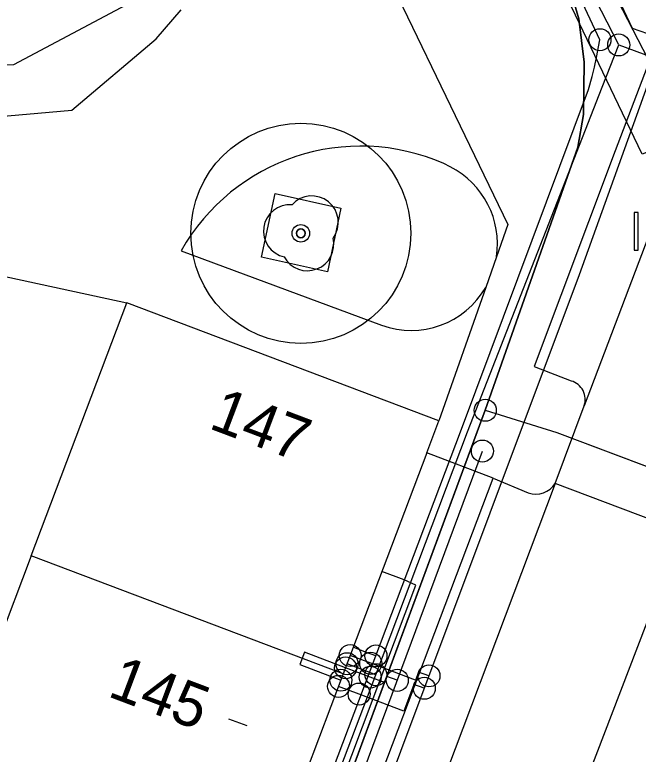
# Model space of a CAD drawing. Extents: x 192672 to 192910, y 446344 to 446512.
# Drawn here: x 192758.05 to 192772.22, y 446479 to 446495.79 of the extents above; entities that cross this region are included whole.
import ezdxf

# ---------------------------------------------------------------- set-up
doc = ezdxf.new("R2010")
doc.units = 0
for name, color, linetype in [('( Toegevoegd 29-11-2021 14_41_42) wegdeel vlak', 7, 'Continuous'), ('B-GV-GR-BOOM-S', 7, 'Continuous'), ('B-OI-KL-()_FIREHYDRANT_WATER-S', 7, 'Continuous'), ('B-OI-KL-()_MANTELBUIS_WATER-G', 7, 'Continuous'), ('B-OI-KL-()_PUNTVANLEVERING_WATER-S', 7, 'Continuous'), ('B-OI-KL-BUISLEIDING_OLIEGASCHEMICALIEN_GASLAGEDRUK-G', 7, 'Continuous'), ('B-OI-KL-DATA-G', 7, 'Continuous'), ('B-OI-KL-DATA_DUCT-G', 7, 'Continuous'), ('B-OI-KL-DATA_GTWP-S', 7, 'Continuous'), ('B-OI-KL-DATA_HULPSTUK-S', 7, 'Continuous'), ('B-OI-KL-DATA_KABELBED-G', 7, 'Continuous'), ('B-OI-KL-DATA_MANTELBUIS-G', 7, 'Continuous'), ('B-OI-KL-DATA_MOF-S', 7, 'Continuous'), ('B-OI-KL-ET_LS-G', 7, 'Continuous'), ('B-OI-KL-ET_LS_DELIVERYPOINT-S', 7, 'Continuous'), ('B-OI-KL-ET_LS_MOF-S', 7, 'Continuous'), ('B-OI-KL-GAS_LD_AFTAKZADEL-S', 7, 'Continuous'), ('B-OI-KL-GAS_LD_DELIVERYPOINT-S', 7, 'Continuous'), ('B-OI-KL-GAS_LD_OVERGANGSSTUK-S', 7, 'Continuous'), ('B-OI-KL-WATER-G', 7, 'Continuous'), ('B-OI-RI-RIOOLVRIJVERVAL-G', 7, 'Continuous'), ('boom', 7, 'Continuous'), ('Default', 7, 'Continuous'), ('huisnummerreeks BGT', 7, 'Continuous'), ('kant open verharding', 7, 'Continuous'), ('kant verharding', 7, 'Continuous'), ('kolk', 7, 'Continuous'), ('pand op maaiveld vlak', 7, 'Continuous'), ('verkeerseiland - berm', 7, 'Continuous')]:
    doc.layers.add(name, color=color, linetype=linetype)

# ---------------------------------------------------------------- blocks, each defined once
blk = doc.blocks.new('B-OI-KL-DATA_HULPSTUK-S')
at = {"layer": 'Default'}
blk.add_circle((0, 0), 0.25, dxfattribs=at)
blk = doc.blocks.new('B-OI-KL-GAS_LD_AFTAKZADEL-S')
at = {"layer": 'Default'}
blk.add_circle((0, 0), 0.25, dxfattribs=at)
blk = doc.blocks.new('B-OI-KL-GAS_LD_DELIVERYPOINT-S')
at = {"layer": 'Default'}
blk.add_circle((0, 0), 0.25, dxfattribs=at)
blk = doc.blocks.new('B-OI-KL-GAS_LD_OVERGANGSSTUK-S')
at = {"layer": 'Default'}
blk.add_circle((0, 0), 0.25, dxfattribs=at)
blk = doc.blocks.new('B-OI-KL-ET_LS_DELIVERYPOINT-S')
at = {"layer": 'Default'}
blk.add_circle((0, 0), 0.25, dxfattribs=at)
blk = doc.blocks.new('B-OI-KL-ET_LS_MOF-S')
at = {"layer": 'Default'}
blk.add_circle((0, 0), 0.25, dxfattribs=at)
blk = doc.blocks.new('B-OI-KL-()_FIREHYDRANT_WATER-S')
at = {"layer": 'Default'}
blk.add_circle((0, 0), 0.25, dxfattribs=at)
blk = doc.blocks.new('B-OI-KL-()_PUNTVANLEVERING_WATER-S')
at = {"layer": 'Default'}
blk.add_circle((0, 0), 0.25, dxfattribs=at)
blk = doc.blocks.new('B-OI-KL-DATA_GTWP-S')
at = {"layer": 'Default'}
blk.add_circle((0, 0), 0.25, dxfattribs=at)
blk = doc.blocks.new('B-OI-KL-DATA_MOF-S')
at = {"layer": 'Default'}
blk.add_circle((0, 0), 0.25, dxfattribs=at)

msp = doc.modelspace()

# ---------------------------------------------------------------- linework, layer by layer
at = {"layer": '( Toegevoegd 29-11-2021 14_41_42) wegdeel vlak'}
msp.add_line((192749.833, 446491.572), (192760.593, 446489.25), dxfattribs=at)
msp.add_lwpolyline([(192765.561, 446498.667), (192758.023, 446494.654), (192749.243, 446494.562), (192737.517, 446496.509), (192736.353, 446498.833), (192734.578, 446497.242), (192732.701, 446497.637), (192731.791, 446499.455)], dxfattribs=at)
at = {"layer": 'B-GV-GR-BOOM-S'}
for radius in [2.5, 0.2]:
    msp.add_circle((192764.55, 446490.826), radius, dxfattribs=at)
at = {"layer": 'B-OI-KL-()_MANTELBUIS_WATER-G'}
msp.add_lwpolyline([(192766.02, 446481.314), (192765.741, 446481.424)], dxfattribs=at)
at = {"layer": 'B-OI-KL-BUISLEIDING_OLIEGASCHEMICALIEN_GASLAGEDRUK-G'}
for points in [[(192770.261, 446499.113), (192771.393, 446496.803), (192772.556, 446494.554), (192770.877, 446489.886), (192758.67, 446457.345), (192745.084, 446421.436), (192742.217, 446413.618)], [(192766.138, 446481.06), (192765.67, 446481.237)], [(192767.46, 446480.775), (192767.226, 446480.863), (192767.156, 446480.676), (192766.138, 446481.06)], [(192765.874, 446480.361), (192765.406, 446480.537)], [(192767.354, 446480.494), (192767.12, 446480.582), (192766.893, 446479.975), (192765.874, 446480.361)]]:
    msp.add_lwpolyline(points, dxfattribs=at)
at = {"layer": 'B-OI-KL-DATA-G'}
for points in [[(192745.236, 446436.264), (192745.276, 446436.371), (192749.491, 446434.791), (192749.794, 446435.599), (192768.74, 446486.807), (192770.369, 446486.306), (192778.924, 446483.081), (192784.343, 446497.176), (192794.941, 446502.078), (192811.396, 446509.756)], [(192757.844, 446425.655), (192756.715, 446426.08), (192759.12, 446432.478), (192750.822, 446435.215), (192749.794, 446435.599), (192768.74, 446486.807), (192770.369, 446486.306), (192778.924, 446483.081), (192784.343, 446497.176), (192794.941, 446502.078), (192811.396, 446509.756)], [(192757.844, 446425.655), (192756.715, 446426.08), (192759.12, 446432.478), (192750.822, 446435.215), (192749.794, 446435.599), (192768.74, 446486.807), (192770.369, 446486.306), (192778.924, 446483.081), (192784.343, 446497.176), (192794.941, 446502.078), (192811.396, 446509.756)], [(192757.844, 446425.655), (192756.715, 446426.08), (192759.12, 446432.478), (192750.822, 446435.215), (192749.794, 446435.599), (192768.74, 446486.807), (192770.369, 446486.306), (192778.924, 446483.081), (192784.343, 446497.176), (192794.941, 446502.078), (192811.396, 446509.756)], [(192757.844, 446425.655), (192756.715, 446426.08), (192759.12, 446432.478), (192750.822, 446435.215), (192749.794, 446435.599), (192768.74, 446486.807), (192770.369, 446486.306), (192778.924, 446483.081), (192784.343, 446497.176), (192794.941, 446502.078), (192811.396, 446509.756)], [(192757.844, 446425.655), (192756.715, 446426.08), (192759.12, 446432.478), (192750.822, 446435.215), (192749.794, 446435.599), (192768.74, 446486.807), (192770.369, 446486.306), (192778.924, 446483.081), (192784.343, 446497.176), (192794.941, 446502.078), (192811.396, 446509.756)], [(192757.844, 446425.655), (192756.715, 446426.08), (192759.12, 446432.478), (192750.822, 446435.215), (192749.794, 446435.599), (192768.74, 446486.807), (192770.369, 446486.306), (192778.924, 446483.081), (192784.343, 446497.176), (192794.941, 446502.078), (192811.396, 446509.756)], [(192757.844, 446425.655), (192756.715, 446426.08), (192759.12, 446432.478), (192750.822, 446435.215), (192749.794, 446435.599), (192768.74, 446486.807), (192770.369, 446486.306), (192778.924, 446483.081), (192784.343, 446497.176), (192794.941, 446502.078), (192811.396, 446509.756)], [(192764.304, 446509.756), (192770.565, 446496.734), (192770.867, 446495.7), (192770.986, 446494.71), (192770.973, 446493.522), (192770.841, 446492.782), (192768.74, 446486.807), (192749.794, 446435.599)], [(192764.304, 446509.756), (192770.565, 446496.734), (192770.867, 446495.7), (192770.986, 446494.71), (192770.973, 446493.522), (192770.841, 446492.782), (192768.74, 446486.807), (192749.794, 446435.599)], [(192764.304, 446509.756), (192770.565, 446496.734), (192770.867, 446495.7), (192770.986, 446494.71), (192770.973, 446493.522), (192770.841, 446492.782), (192768.74, 446486.807), (192749.794, 446435.599)], [(192764.304, 446509.756), (192770.565, 446496.734), (192770.867, 446495.7), (192770.986, 446494.71), (192770.973, 446493.522), (192770.841, 446492.782), (192768.74, 446486.807), (192749.794, 446435.599)], [(192764.304, 446509.756), (192770.565, 446496.734), (192770.867, 446495.7), (192770.986, 446494.71), (192770.973, 446493.522), (192770.841, 446492.782), (192768.74, 446486.807), (192749.794, 446435.599)], [(192764.304, 446509.756), (192770.565, 446496.734), (192770.867, 446495.7), (192770.986, 446494.71), (192770.973, 446493.522), (192770.841, 446492.782), (192768.74, 446486.807), (192749.794, 446435.599)], [(192764.304, 446509.756), (192770.565, 446496.734), (192770.867, 446495.7), (192770.986, 446494.71), (192770.973, 446493.522), (192770.841, 446492.782), (192768.74, 446486.807), (192749.794, 446435.599)], [(192764.304, 446509.756), (192770.565, 446496.734), (192770.867, 446495.7), (192770.986, 446494.71), (192770.973, 446493.522), (192770.841, 446492.782), (192768.74, 446486.807), (192749.794, 446435.599)], [(192764.304, 446509.756), (192770.565, 446496.734), (192770.867, 446495.7), (192770.986, 446494.71), (192770.973, 446493.522), (192770.841, 446492.782), (192768.74, 446486.807), (192749.794, 446435.599)], [(192764.304, 446509.756), (192770.565, 446496.734), (192770.867, 446495.7), (192770.986, 446494.71), (192770.973, 446493.522), (192770.841, 446492.782), (192768.74, 446486.807), (192749.794, 446435.599)], [(192764.304, 446509.756), (192770.565, 446496.734), (192770.867, 446495.7), (192770.986, 446494.71), (192770.973, 446493.522), (192770.841, 446492.782), (192768.74, 446486.807), (192749.794, 446435.599)], [(192764.304, 446509.756), (192770.565, 446496.734), (192770.867, 446495.7), (192770.986, 446494.71), (192770.973, 446493.522), (192770.841, 446492.782), (192768.74, 446486.807), (192749.794, 446435.599)], [(192764.304, 446509.756), (192770.565, 446496.734), (192770.867, 446495.7), (192770.986, 446494.71), (192770.973, 446493.522), (192770.841, 446492.782), (192768.74, 446486.807), (192749.794, 446435.599)], [(192764.304, 446509.756), (192770.565, 446496.734), (192770.867, 446495.7), (192770.986, 446494.71), (192770.973, 446493.522), (192770.841, 446492.782), (192768.74, 446486.807), (192749.794, 446435.599)], [(192764.304, 446509.756), (192770.565, 446496.734), (192770.867, 446495.7), (192770.986, 446494.71), (192770.973, 446493.522), (192770.841, 446492.782), (192768.74, 446486.807), (192749.794, 446435.599)], [(192764.304, 446509.756), (192770.565, 446496.734), (192770.867, 446495.7), (192770.986, 446494.71), (192770.973, 446493.522), (192770.841, 446492.782), (192768.74, 446486.807), (192770.369, 446486.306), (192778.924, 446483.081), (192784.343, 446497.176), (192794.941, 446502.078), (192809.504, 446508.873), (192809.089, 446509.756)], [(192764.304, 446509.756), (192770.565, 446496.734), (192770.867, 446495.7), (192770.986, 446494.71), (192770.973, 446493.522), (192770.841, 446492.782), (192768.74, 446486.807), (192770.369, 446486.306), (192778.924, 446483.081), (192784.343, 446497.176), (192794.941, 446502.078), (192809.504, 446508.873), (192809.089, 446509.756)], [(192768.74, 446486.807), (192770.841, 446492.782), (192770.973, 446493.522), (192770.986, 446494.71), (192770.867, 446495.7), (192770.565, 446496.734), (192764.304, 446509.756)], [(192768.74, 446486.807), (192770.841, 446492.782), (192770.973, 446493.522), (192770.986, 446494.71), (192770.867, 446495.7), (192770.565, 446496.734), (192764.304, 446509.756)], [(192764.304, 446509.756), (192770.565, 446496.734), (192770.867, 446495.7), (192770.986, 446494.71), (192770.973, 446493.522), (192770.841, 446492.782), (192768.74, 446486.807)], [(192764.304, 446509.756), (192770.565, 446496.734), (192770.867, 446495.7), (192770.986, 446494.71), (192770.973, 446493.522), (192770.841, 446492.782), (192768.74, 446486.807)], [(192768.74, 446486.807), (192770.369, 446486.306), (192778.924, 446483.081), (192784.343, 446497.176), (192794.941, 446502.078), (192811.396, 446509.756)], [(192768.74, 446486.807), (192770.369, 446486.306), (192778.924, 446483.081), (192784.343, 446497.176), (192794.941, 446502.078), (192809.266, 446508.761), (192809.501, 446508.269)], [(192768.74, 446486.807), (192749.794, 446435.599), (192742.072, 446415.039), (192739.06, 446406.841), (192720.2, 446413.77), (192719.012, 446414.118), (192696.077, 446422.823), (192683.193, 446427.673), (192678.122, 446429.261), (192675.743, 446430.156)], [(192733.785, 446392.743), (192734.518, 446394.712), (192733.684, 446396.245), (192736.06, 446402.723), (192736.56, 446403.025), (192737.067, 446403.408), (192737.543, 446403.858), (192738.002, 446404.406), (192738.438, 446405.088), (192738.75, 446405.758), (192738.917, 446406.249), (192739.06, 446406.841), (192742.072, 446415.039), (192749.794, 446435.599), (192768.74, 446486.807)], [(192768.74, 446486.807), (192749.794, 446435.599), (192749.491, 446434.791), (192745.276, 446436.371), (192745.236, 446436.264)], [(192757.844, 446425.655), (192756.715, 446426.08), (192759.12, 446432.478), (192750.822, 446435.215), (192749.794, 446435.599), (192768.74, 446486.807)], [(192765.468, 446478.329), (192767.16, 446482.837), (192766.899, 446482.955), (192766.393, 446483.147)], [(192762.908, 446479.799), (192763.325, 446479.648)]]:
    msp.add_lwpolyline(points, dxfattribs=at)
at = {"layer": 'B-OI-KL-DATA_DUCT-G'}
msp.add_lwpolyline([(192770.369, 446486.306), (192777.571, 446483.59)], dxfattribs=at)
at = {"layer": 'B-OI-KL-DATA_KABELBED-G'}
for points in [[(192771.773, 446495.105), (192769.257, 446500), (192768.58, 446501.319), (192765.703, 446507.336), (192765.488, 446507.787), (192764.547, 446509.756)], [(192768.74, 446486.807), (192770.841, 446492.782), (192770.973, 446493.522), (192770.986, 446494.71), (192770.867, 446495.7), (192770.565, 446496.734), (192767.214, 446503.702)], [(192758.244, 446458.849), (192758.401, 446459.269), (192759.635, 446462.561), (192759.785, 446463.69), (192760.846, 446466.496), (192762.737, 446471.498), (192765, 446477.485), (192766.254, 446480.802), (192768.34, 446486.321), (192771.398, 446494.146), (192771.773, 446495.105)], [(192771.773, 446495.105), (192781.702, 446491.432), (192782.051, 446491.343), (192782.052, 446491.343)], [(192760.694, 446465.06), (192768.74, 446486.807)], [(192768.74, 446486.807), (192770.369, 446486.306)], [(192770.369, 446486.306), (192777.571, 446483.59)], [(192766.254, 446480.802), (192765.6, 446481.05)], [(192762.908, 446479.799), (192763.325, 446479.648)]]:
    msp.add_lwpolyline(points, dxfattribs=at)
at = {"layer": 'B-OI-KL-DATA_MANTELBUIS-G'}
msp.add_lwpolyline([(192770.369, 446486.306), (192777.571, 446483.59)], dxfattribs=at)
at = {"layer": 'B-OI-KL-ET_LS-G'}
for points in [[(192774.175, 446493.36), (192772.308, 446492.626), (192764.089, 446509.756)], [(192807.795, 446509.756), (192785.465, 446499.231), (192784.279, 446497.948), (192782.198, 446492.212), (192772.784, 446495.238), (192772.082, 446495.48), (192769.274, 446501.433)], [(192738.378, 446496.142), (192739.482, 446495.624), (192753.92, 446493.148), (192759.346, 446493.622), (192761.266, 446495.244), (192761.834, 446495.904)], [(192737.952, 446406.43), (192738.358, 446406.675), (192738.717, 446406.983), (192739.022, 446407.347), (192739.262, 446407.755), (192739.381, 446408.001), (192760.347, 446463.479), (192768.676, 446485.881)], [(192765.565, 446480.958), (192764.63, 446481.312), (192764.523, 446481.031), (192765.459, 446480.677)], [(192766.126, 446480.746), (192765.565, 446480.958)], [(192766.74, 446480.674), (192766.505, 446480.762), (192766.454, 446480.622), (192766.126, 446480.746)]]:
    msp.add_lwpolyline(points, dxfattribs=at)
at = {"layer": 'B-OI-KL-WATER-G'}
for points in [[(192771.346, 446495.222), (192767.273, 446503.913)], [(192741.742, 446414.91), (192745.233, 446424.477), (192759.645, 446463.744), (192768.2, 446486.375), (192771.087, 446494.09), (192771.168, 446494.386), (192771.221, 446494.601), (192771.269, 446494.816), (192771.346, 446495.222)], [(192766.255, 446481.23), (192766.02, 446481.314), (192765.741, 446481.424)]]:
    msp.add_lwpolyline(points, dxfattribs=at)
at = {"layer": 'B-OI-RI-RIOOLVRIJVERVAL-G'}
msp.add_lwpolyline([(192759.86, 446449.26), (192779.05, 446499.28)], dxfattribs=at)
at = {"layer": 'boom'}
msp.add_circle((192764.55, 446490.826), 0.1, dxfattribs=at)
for centre, radius, start, end in [((192764.8, 446491.076), 0.6, 323.5446, 138.4658), ((192764.3, 446490.876), 0.6, 85.137, 257.7544), ((192764.55, 446490.826), 0.1, 0, 180), ((192764.55, 446490.826), 0.1, 180, 0), ((192764.7, 446490.576), 0.6, 208.5058, 13.8356)]:
    msp.add_arc(centre, radius, start, end, dxfattribs=at)
at = {"layer": 'kant open verharding'}
for p, q in [((192768.751, 446489.598), (192767.686, 446486.569)), ((192770.332, 446485.145), (192770.985, 446486.905)), ((192768.919, 446485.267), (192767.41, 446485.838)), ((192776.448, 446482.826), (192770.332, 446485.145))]:
    msp.add_line(p, q, dxfattribs=at)
msp.add_lwpolyline([(192765.561, 446498.667), (192769.255, 446491.03), (192768.995, 446490.291)], dxfattribs=at)
at = {"layer": 'kant verharding'}
for p, q in [((192768.919, 446485.267), (192769.718, 446484.933)), ((192770.332, 446485.145), (192761.884, 446462.784))]:
    msp.add_line(p, q, dxfattribs=at)
msp.add_lwpolyline([(192761.621, 446463.349), (192760.755, 446463.677), (192768.919, 446485.267)], dxfattribs=at)
msp.add_arc((192769.888, 446485.436), 0.531, 251.3114, 326.7858, dxfattribs=at)
at = {"layer": 'kolk'}
msp.add_lwpolyline([(192772.212, 446490.872), (192772.212, 446491.297), (192772.127, 446491.297), (192772.127, 446490.872), (192772.127, 446490.447), (192772.212, 446490.447)], close=True, dxfattribs=at)
at = {"layer": 'pand op maaiveld vlak'}
for p, q in [((192758.419, 446483.499), (192760.593, 446489.25)), ((192767.686, 446486.569), (192760.593, 446489.25)), ((192767.41, 446485.838), (192767.686, 446486.569)), ((192767.41, 446485.838), (192765.512, 446480.818)), ((192758.419, 446483.499), (192756.316, 446477.935)), ((192765.512, 446480.818), (192758.419, 446483.499)), ((192765.512, 446480.818), (192763.408, 446475.254))]:
    msp.add_line(p, q, dxfattribs=at)
at = {"layer": 'verkeerseiland - berm'}
for p, q in [((192767.944, 446492.335), (192767.801, 446492.408)), ((192761.828, 446490.429), (192766.384, 446488.738)), ((192768.995, 446490.291), (192768.751, 446489.598))]:
    msp.add_line(p, q, dxfattribs=at)
for points in [[(192773.367, 446497.097), (192771.694, 446492.7), (192769.851, 446487.804), (192770.692, 446487.472)], [(192773.367, 446497.097), (192773.526, 446496.058), (192773.566, 446495.048), (192773.494, 446493.942), (192773.307, 446493.007), (192770.985, 446486.905)], [(192763.963, 446491.728), (192765.459, 446491.398), (192765.155, 446489.951), (192763.659, 446490.281), (192763.963, 446491.728)]]:
    msp.add_lwpolyline(points, dxfattribs=at)
for centre, radius, start, end in [((192765.91, 446488.113), 4.693, 66.2315, 150.431), ((192767.055, 446490.586), 1.963, 351.3683, 63.0551), ((192767.053, 446490.585), 1.964, 250.1006, 329.8345), ((192770.578, 446487.054), 0.433, 339.8875, 74.7682)]:
    msp.add_arc(centre, radius, start, end, dxfattribs=at)

# ---------------------------------------------------------------- block references
at = {"layer": 'B-OI-KL-()_FIREHYDRANT_WATER-S'}
msp.add_blockref('B-OI-KL-()_FIREHYDRANT_WATER-S', (192771.346, 446495.222), dxfattribs=at)
at = {"layer": 'B-OI-KL-()_PUNTVANLEVERING_WATER-S'}
msp.add_blockref('B-OI-KL-()_PUNTVANLEVERING_WATER-S', (192766.255, 446481.23), dxfattribs=at)
at = {"layer": 'B-OI-KL-DATA_GTWP-S'}
for p in [(192771.773, 446495.105), (192771.773, 446495.105), (192771.773, 446495.105), (192765.6, 446481.05), (192766.254, 446480.802)]:
    msp.add_blockref('B-OI-KL-DATA_GTWP-S', p, dxfattribs=at)
at = {"layer": 'B-OI-KL-DATA_HULPSTUK-S'}
msp.add_blockref('B-OI-KL-DATA_HULPSTUK-S', (192768.74, 446486.807), dxfattribs=at)
at = {"layer": 'B-OI-KL-DATA_MOF-S'}
msp.add_blockref('B-OI-KL-DATA_MOF-S', (192766.254, 446480.802), dxfattribs=at)
at = {"layer": 'B-OI-KL-ET_LS_DELIVERYPOINT-S'}
for p in [(192765.565, 446480.958), (192765.459, 446480.677)]:
    msp.add_blockref('B-OI-KL-ET_LS_DELIVERYPOINT-S', p, dxfattribs=at)
at = {"layer": 'B-OI-KL-ET_LS_MOF-S'}
for p in [(192768.676, 446485.881), (192766.126, 446480.746), (192766.74, 446480.674)]:
    msp.add_blockref('B-OI-KL-ET_LS_MOF-S', p, dxfattribs=at)
at = {"layer": 'B-OI-KL-GAS_LD_AFTAKZADEL-S'}
for p in [(192767.46, 446480.775), (192767.354, 446480.494)]:
    msp.add_blockref('B-OI-KL-GAS_LD_AFTAKZADEL-S', p, dxfattribs=at)
at = {"layer": 'B-OI-KL-GAS_LD_DELIVERYPOINT-S'}
for p in [(192765.67, 446481.237), (192765.406, 446480.537)]:
    msp.add_blockref('B-OI-KL-GAS_LD_DELIVERYPOINT-S', p, dxfattribs=at)
at = {"layer": 'B-OI-KL-GAS_LD_OVERGANGSSTUK-S'}
for p in [(192766.138, 446481.06), (192765.874, 446480.361)]:
    msp.add_blockref('B-OI-KL-GAS_LD_OVERGANGSSTUK-S', p, dxfattribs=at)

# ---------------------------------------------------------------- texts
at = {"layer": 'huisnummerreeks BGT'}
for s, p in [('147', (192762.431, 446486.407)), ('145', (192760.132, 446480.321))]:
    msp.add_text(s, height=1, rotation=339.3, dxfattribs=at).set_placement(p)

doc.saveas('drawing.dxf')
